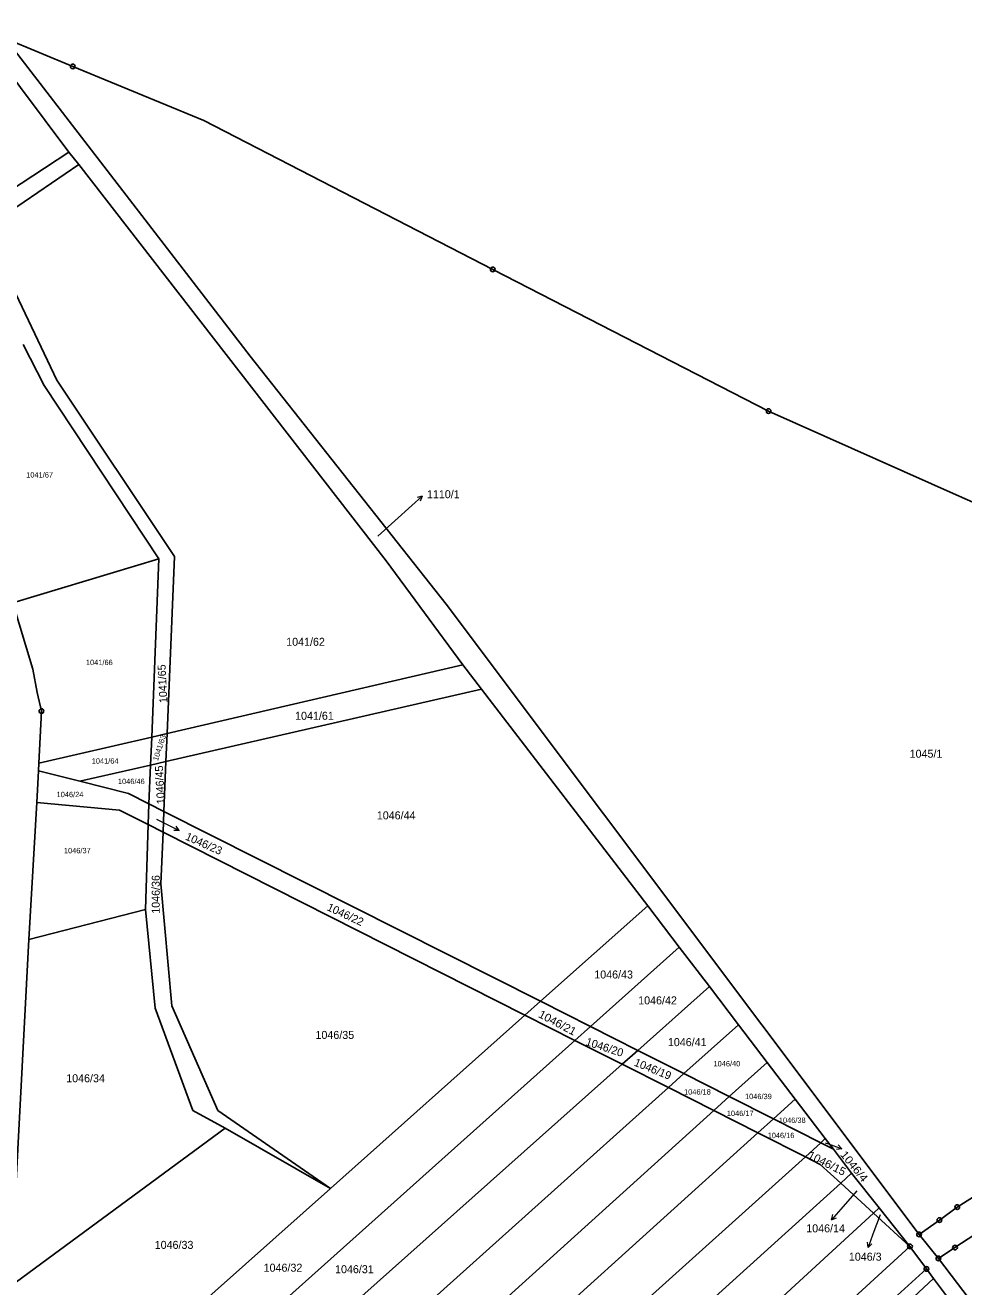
# Model space of a CAD drawing. Extents: x -694609 to -690140, y -1033292 to -1029794.
# Drawn here: x -690925.2 to -690725.9, y -1031744.2 to -1031476.2 of the extents above; entities that cross this region are included whole.
import ezdxf
from ezdxf.enums import TextEntityAlignment as Align

# ---------------------------------------------------------------- set-up
doc = ezdxf.new("R2010")
doc.units = 0
doc.header["$LTSCALE"] = 0.68
for name, color, linetype, lineweight in [('1', 7, 'Continuous', 25), ('7', 7, 'Continuous', 13), ('8', 7, 'Continuous', 25)]:
    doc.layers.add(name, color=color, linetype=linetype, lineweight=lineweight)
doc.layers.add('2', color=7, linetype='Continuous')

msp = doc.modelspace()

# ---------------------------------------------------------------- linework, layer by layer
at = {"layer": '1'}
for p, q in [((-690915.94, -1031503.17), (-690936.17, -1031476.19)), ((-690877.44, -1031546.54), (-690929.43, -1031478.99)), ((-690929.43, -1031478.99), (-690915.12, -1031484.95)), ((-690915.12, -1031484.95), (-690887.28, -1031496.41)), ((-690887.28, -1031496.41), (-690825.92, -1031528.06)), ((-690937.57, -1031517.29), (-690915.94, -1031503.17)), ((-690913.87, -1031505.78), (-690915.94, -1031503.17)), ((-690933.81, -1031519.44), (-690913.87, -1031505.78)), ((-690848.55, -1031589.96), (-690913.87, -1031505.78)), ((-690918.48, -1031551.64), (-690933.81, -1031519.44)), ((-690825.92, -1031528.06), (-690767.33, -1031558.17)), ((-690921.19, -1031552.75), (-690925.64, -1031544.06)), ((-690835.84, -1031599.22), (-690877.44, -1031546.54)), ((-690893.49, -1031589.04), (-690918.48, -1031551.64)), ((-690896.83, -1031589.54), (-690921.19, -1031552.75)), ((-690767.33, -1031558.17), (-690726.81, -1031576.22)), ((-690726.81, -1031576.22), (-690706.91, -1031585.09)), ((-690927.87, -1031598.9), (-690896.83, -1031589.54)), ((-690898.36, -1031627.43), (-690896.83, -1031589.54)), ((-690895.07, -1031626.67), (-690893.49, -1031589.04)), ((-690832.29, -1031612.1), (-690848.55, -1031589.96)), ((-690923.64, -1031613.04), (-690927.87, -1031598.9)), ((-690735.34, -1031733.1), (-690835.84, -1031599.22)), ((-690922.66, -1031617.94), (-690923.64, -1031613.04)), ((-690895.07, -1031626.67), (-690832.29, -1031612.1)), ((-690828.33, -1031617.25), (-690832.29, -1031612.1)), ((-690921.77, -1031621.9), (-690922.66, -1031617.94)), ((-690895.32, -1031632.63), (-690828.33, -1031617.25)), ((-690793, -1031663.28), (-690828.33, -1031617.25)), ((-690922.33, -1031633), (-690921.77, -1031621.9)), ((-690922.33, -1031633), (-690898.36, -1031627.43)), ((-690898.6, -1031633.38), (-690898.36, -1031627.43)), ((-690898.36, -1031627.43), (-690895.07, -1031626.67)), ((-690895.32, -1031632.63), (-690895.07, -1031626.67)), ((-690898.6, -1031633.38), (-690895.32, -1031632.63)), ((-690895.76, -1031643.22), (-690895.32, -1031632.63)), ((-690922.43, -1031634.58), (-690922.74, -1031641.35)), ((-690922.43, -1031634.58), (-690922.33, -1031633)), ((-690922.43, -1031634.58), (-690913.59, -1031636.82)), ((-690913.59, -1031636.82), (-690898.6, -1031633.38)), ((-690898.93, -1031641.62), (-690898.6, -1031633.38)), ((-690913.59, -1031636.82), (-690903.29, -1031639.42)), ((-690903.29, -1031639.42), (-690898.93, -1031641.62)), ((-690924.48, -1031670.48), (-690922.74, -1031641.35)), ((-690905.21, -1031642.96), (-690922.74, -1031641.35)), ((-690899.11, -1031646.02), (-690905.21, -1031642.96)), ((-690899.11, -1031646.02), (-690898.93, -1031641.62)), ((-690898.93, -1031641.62), (-690895.76, -1031643.22)), ((-690895.95, -1031647.64), (-690895.76, -1031643.22)), ((-690899.65, -1031664.1), (-690899.11, -1031646.02)), ((-690895.95, -1031647.64), (-690899.11, -1031646.02)), ((-690896.41, -1031658.64), (-690895.95, -1031647.64)), ((-690819.07, -1031686.51), (-690895.95, -1031647.64)), ((-690894.06, -1031684.53), (-690896.41, -1031658.64)), ((-690899.65, -1031664.1), (-690924.48, -1031670.48)), ((-690897.59, -1031685.04), (-690899.65, -1031664.1)), ((-690793, -1031663.28), (-690815.78, -1031683.57)), ((-690786.3, -1031672.06), (-690793, -1031663.28)), ((-690927.26, -1031724.52), (-690924.48, -1031670.48)), ((-690786.3, -1031672.06), (-690805.16, -1031688.93)), ((-690779.89, -1031680.46), (-690786.3, -1031672.06)), ((-690779.89, -1031680.46), (-690795.1, -1031694.01)), ((-690773.72, -1031688.55), (-690779.89, -1031680.46)), ((-690815.78, -1031683.57), (-690819.07, -1031686.51)), ((-690889.63, -1031706.81), (-690897.59, -1031685.04)), ((-690884.29, -1031706.75), (-690894.06, -1031684.53)), ((-690819.07, -1031686.51), (-690860.41, -1031723.34)), ((-690808.46, -1031691.88), (-690819.07, -1031686.51)), ((-690805.16, -1031688.93), (-690808.46, -1031691.88)), ((-690805.16, -1031688.93), (-690795.1, -1031694.01)), ((-690773.72, -1031688.55), (-690785.31, -1031698.95)), ((-690767.62, -1031696.55), (-690773.72, -1031688.55)), ((-690727.23, -1031727.32), (-690664.94, -1031687.82)), ((-690808.46, -1031691.88), (-690903.16, -1031776.6)), ((-690798.41, -1031696.96), (-690808.46, -1031691.88)), ((-690795.1, -1031694.01), (-690798.41, -1031696.96)), ((-690795.1, -1031694.01), (-690785.31, -1031698.95)), ((-690788.61, -1031701.91), (-690798.41, -1031696.96)), ((-690775.66, -1031703.82), (-690767.62, -1031696.55)), ((-690761.66, -1031704.36), (-690767.62, -1031696.55)), ((-690785.31, -1031698.95), (-690788.61, -1031701.91)), ((-690785.31, -1031698.95), (-690775.66, -1031703.82)), ((-690788.61, -1031701.91), (-690888.54, -1031791.59)), ((-690778.95, -1031706.8), (-690788.61, -1031701.91)), ((-690778.95, -1031706.8), (-690775.66, -1031703.82)), ((-690775.66, -1031703.82), (-690766.29, -1031708.55)), ((-690761.66, -1031704.36), (-690766.29, -1031708.55)), ((-690755.27, -1031712.73), (-690761.66, -1031704.36)), ((-690882.73, -1031710.56), (-690889.63, -1031706.81)), ((-690860.41, -1031723.34), (-690884.29, -1031706.75)), ((-690769.59, -1031711.53), (-690778.95, -1031706.8)), ((-690927.09, -1031743.17), (-690882.73, -1031710.56)), ((-690860.41, -1031723.34), (-690882.73, -1031710.56)), ((-690766.29, -1031708.55), (-690769.59, -1031711.53)), ((-690766.29, -1031708.55), (-690756.24, -1031713.62)), ((-690769.59, -1031711.53), (-690874.34, -1031806.16)), ((-690759.51, -1031716.63), (-690769.59, -1031711.53)), ((-690756.24, -1031713.62), (-690755.27, -1031712.73)), ((-690753.56, -1031714.97), (-690755.27, -1031712.73)), ((-690759.51, -1031716.63), (-690756.24, -1031713.62)), ((-690756.24, -1031713.62), (-690753.56, -1031714.97)), ((-690749.67, -1031720.08), (-690753.56, -1031714.97)), ((-690759.51, -1031716.63), (-690867.15, -1031813.54)), ((-690756.33, -1031718.24), (-690759.51, -1031716.63)), ((-690752, -1031722.19), (-690756.33, -1031718.24)), ((-690752, -1031722.19), (-690749.67, -1031720.08)), ((-690743.8, -1031727.46), (-690749.67, -1031720.08)), ((-690860.41, -1031723.34), (-690911.07, -1031768.48)), ((-690860.45, -1031820.41), (-690752, -1031722.19)), ((-690745.01, -1031728.59), (-690752, -1031722.19)), ((-690853.24, -1031827.81), (-690745.01, -1031728.59)), ((-690745.01, -1031728.59), (-690743.8, -1031727.46)), ((-690737.28, -1031735.66), (-690745.01, -1031728.59)), ((-690737.28, -1031735.66), (-690743.8, -1031727.46)), ((-690731.04, -1031730.07), (-690727.23, -1031727.32)), ((-690735.34, -1031733.1), (-690731.04, -1031730.07)), ((-690731.23, -1031738.21), (-690735.34, -1031733.1)), ((-690727.72, -1031735.91), (-690723.5, -1031733.14)), ((-690846.11, -1031835.13), (-690737.28, -1031735.66)), ((-690733.79, -1031740.43), (-690737.28, -1031735.66)), ((-690731.23, -1031738.21), (-690727.72, -1031735.91)), ((-690712.47, -1031762.82), (-690731.23, -1031738.21)), ((-690733.79, -1031740.43), (-690877.17, -1031870.27)), ((-690764.79, -1031772.78), (-690732.32, -1031742.45)), ((-690732.32, -1031742.45), (-690733.79, -1031740.43)), ((-690727.2, -1031749.25), (-690732.32, -1031742.45))]:
    msp.add_line(p, q, dxfattribs=at)
for points in [[(-690895.76, -1031643.22), (-690815.78, -1031683.57), (-690805.16, -1031688.93)], [(-690798.41, -1031696.96), (-690896, -1031783.94), (-690888.54, -1031791.59)], [(-690907.25, -1031822.8), (-690881.13, -1031799.19), (-690778.95, -1031706.8)]]:
    msp.add_lwpolyline(points, dxfattribs=at)
at = {"layer": '7'}
for p, q in [((-690840.89, -1031576.262), (-690841.969, -1031576.56)), ((-690892.516, -1031647.292), (-690893.181, -1031646.392)), ((-690751.78, -1031714.906), (-690752.55, -1031714.093)), ((-690753.959, -1031729.995), (-690752.924, -1031729.568)), ((-690746.186, -1031735.88), (-690745.373, -1031735.11))]:
    msp.add_line(p, q, dxfattribs=at)
for points in [[(-690850.31, -1031584.76), (-690843.12, -1031578.27), (-690840.89, -1031576.262), (-690841.299, -1031577.304)], [(-690897.32, -1031644.85), (-690895.19, -1031645.93), (-690892.516, -1031647.292), (-690893.636, -1031647.284)], [(-690755.28, -1031713.63), (-690754.6, -1031713.88), (-690751.78, -1031714.906), (-690752.892, -1031715.034)], [(-690748.55, -1031723.83), (-690751.99, -1031727.73), (-690753.959, -1031729.995), (-690753.68, -1031728.911)], [(-690743.63, -1031728.96), (-690745.16, -1031733.06), (-690746.186, -1031735.88), (-690746.314, -1031734.768)]]:
    msp.add_lwpolyline(points, dxfattribs=at)
at = {"layer": '8'}
for centre, radius in [((-690915.12, -1031484.9499), 0.5), ((-690915.12, -1031484.9499), 0.0303), ((-690825.92, -1031528.0599), 0.5), ((-690825.92, -1031528.0599), 0.0303), ((-690767.33, -1031558.1699), 0.5), ((-690767.33, -1031558.1699), 0.0303), ((-690921.77, -1031621.8999), 0.5), ((-690921.77, -1031621.8999), 0.0303), ((-690727.23, -1031727.3199), 0.5), ((-690727.23, -1031727.3199), 0.0303), ((-690731.04, -1031730.0699), 0.5), ((-690731.04, -1031730.0699), 0.0303), ((-690735.34, -1031733.0999), 0.5), ((-690735.34, -1031733.0999), 0.0303), ((-690737.28, -1031735.6599), 0.5), ((-690737.28, -1031735.6599), 0.0303), ((-690727.72, -1031735.9099), 0.5), ((-690727.72, -1031735.9099), 0.0303), ((-690733.79, -1031740.4299), 0.5), ((-690731.23, -1031738.2099), 0.5), ((-690731.23, -1031738.2099), 0.0303), ((-690733.79, -1031740.4299), 0.0303)]:
    msp.add_circle(centre, radius, dxfattribs=at)

# ---------------------------------------------------------------- texts
at = {"layer": '2'}
for s, height, p in [('1041/67', 1.14, (-690922.16, -1031572.295)), ('1041/62', 1.7, (-690865.679, -1031608.045)), ('1041/66', 1.14, (-690909.48, -1031612.145)), ('1041/61', 1.7, (-690863.789, -1031623.765)), ('1045/1', 1.7, (-690733.88, -1031631.825)), ('1041/64', 1.14, (-690908.25, -1031633.085)), ('1046/46', 1.14, (-690902.68, -1031637.425)), ('1046/24', 1.14, (-690915.71, -1031640.205)), ('1046/44', 1.7, (-690846.429, -1031644.925)), ('1046/37', 1.14, (-690914.15, -1031652.125)), ('1046/43', 1.7, (-690800.239, -1031678.735)), ('1046/42', 1.7, (-690790.909, -1031684.235)), ('1046/35', 1.7, (-690859.459, -1031691.575)), ('1046/41', 1.7, (-690784.599, -1031693.105)), ('1046/40', 1.14, (-690776.17, -1031697.405)), ('1046/34', 1.7, (-690912.409, -1031700.785)), ('1046/18', 1.14, (-690782.43, -1031703.395)), ('1046/39', 1.14, (-690769.48, -1031704.365)), ('1046/17', 1.14, (-690773.35, -1031707.965)), ('1046/38', 1.14, (-690762.29, -1031709.425)), ('1046/16', 1.14, (-690764.67, -1031712.645)), ('1046/14', 1.7, (-690755.209, -1031732.675)), ('1046/33', 1.7, (-690893.609, -1031736.185)), ('1046/3', 1.7, (-690746.79, -1031738.695)), ('1046/32', 1.7, (-690870.469, -1031741.035)), ('1046/31', 1.7, (-690855.299, -1031741.355))]:
    msp.add_text(s, height=height, dxfattribs=at).set_placement(p, align=Align.CENTER)
msp.add_text('1110/1', height=1.7, dxfattribs=at).set_placement((-690839.89, -1031576.685))
for s, height, rotation, p in [('1041/65', 1.7, 93, (-690895.2166, -1031616.0645)), ('1041/63', 1.14, 72, (-690896.1689, -1031629.8776)), ('1046/45', 1.7, 93, (-690895.7666, -1031637.5545)), ('1046/23', 1.7, 336, (-690887.6167, -1031650.8455)), ('1046/36', 1.7, 90, (-690896.645, -1031660.869)), ('1046/22', 1.7, 335, (-690857.5567, -1031665.8994)), ('1046/20', 1.7, 342, (-690802.4067, -1031694.1275)), ('1046/19', 1.7, 338, (-690792.2264, -1031698.7492))]:
    msp.add_text(s, height=height, rotation=rotation, dxfattribs=at).set_placement(p, align=Align.CENTER)
for s, rotation, width, p in [('1046/21', 332, 1.05, (-690812.5556, -1031688.8924)), ('1046/15', 333, 1.05, (-690755.2964, -1031718.7579)), ('1046/4', 309, 1.1, (-690749.7991, -1031719.1691))]:
    msp.add_text(s, height=1.7, rotation=rotation, dxfattribs=dict(at, width=width)).set_placement(p, align=Align.CENTER)

doc.saveas('drawing.dxf')
